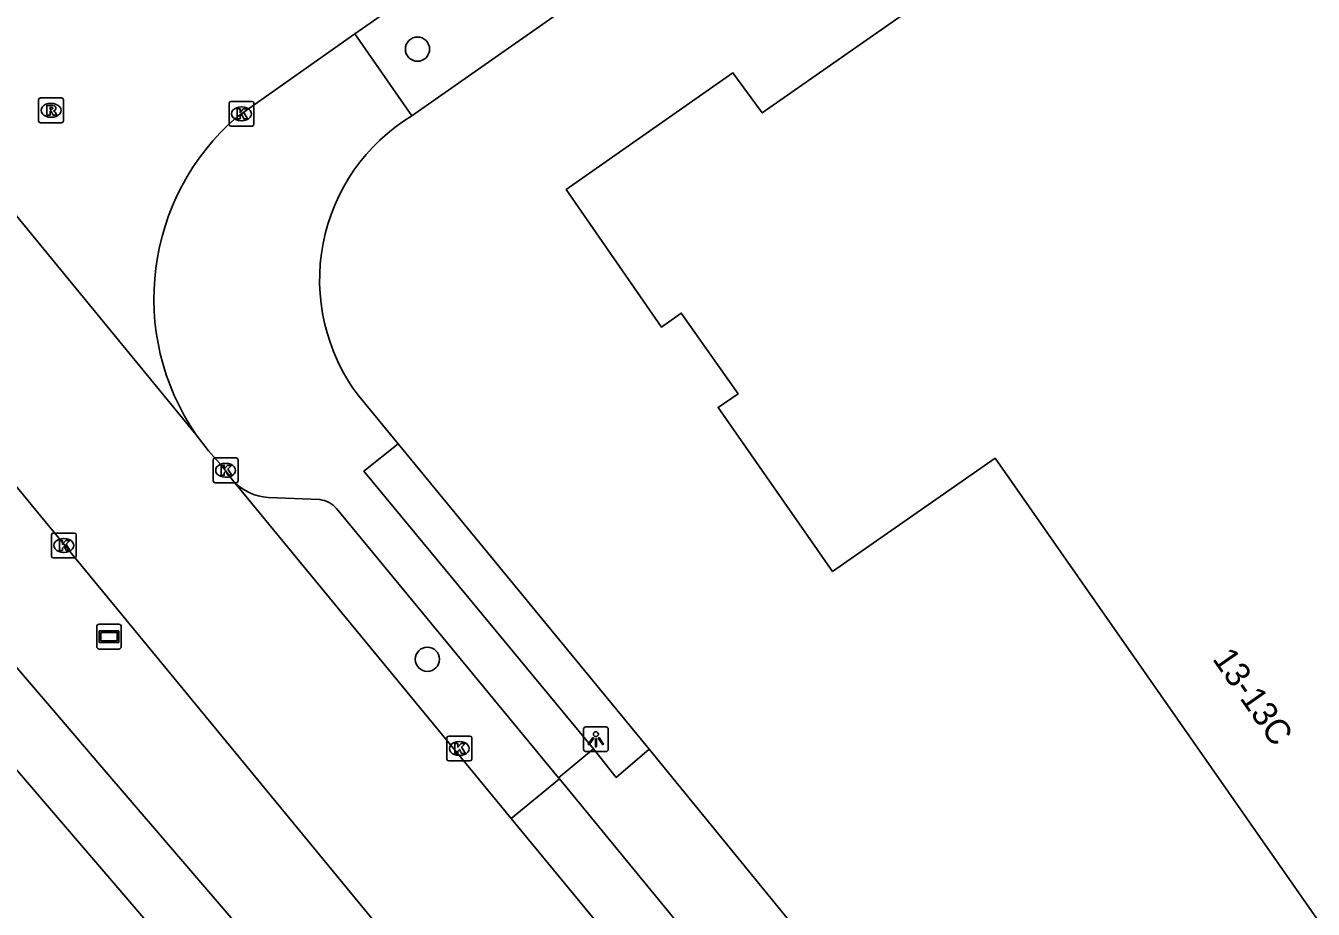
# Model space of a CAD drawing. Extents: x 156651 to 158072, y 387631 to 388990.
# Drawn here: x 157099.8 to 157151.7, y 387934.7 to 387970.3 of the extents above; entities that cross this region are included whole.
import ezdxf

# ---------------------------------------------------------------- set-up
doc = ezdxf.new("R2010")
doc.units = 0
for name, color, linetype in [('IMGEO_Berm_groen', 7, 'Continuous'), ('IMGEO_Boom', 7, 'Continuous'), ('IMGEO_Groenvoorziening', 7, 'Continuous'), ('IMGEO_Kolk', 7, 'Continuous'), ('IMGEO_Lichtpunt', 7, 'Continuous'), ('IMGEO_Pand', 7, 'Continuous'), ('IMGEO_Pand_nummerreeks', 7, 'Continuous'), ('IMGEO_Rijbaan_lokaal_gesloten', 7, 'Continuous'), ('IMGEO_Rioolput', 7, 'Continuous'), ('IMGEO_Spoorbaan_halfverhard', 7, 'Continuous'), ('IMGEO_Verklikker', 7, 'Continuous'), ('IMGEO_Voetpad_open', 7, 'Continuous')]:
    doc.layers.add(name, color=color, linetype=linetype)

msp = doc.modelspace()

# ---------------------------------------------------------------- linework, layer by layer
at = {"layer": 'IMGEO_Berm_groen'}
for points in [[(157115.369, 387966.676), (157132.369, 387978.596)], [(157097.859, 387946.262), (157101.164, 387942.415), (157102.794, 387940.504), (157114.273, 387927.11), (157115.959, 387925.21), (157120.786, 387919.425), (157132.177, 387905.879), (157138.683, 387898.173), (157156.546, 387876.96), (157159.776, 387873.028), (157164.591, 387867.234), (157166.179, 387865.286)]]:
    msp.add_lwpolyline(points, dxfattribs=at)
at = {"layer": 'IMGEO_Boom'}
for centre in [(157115.594, 387969.362), (157115.994, 387944.76)]:
    msp.add_circle(centre, 0.489, dxfattribs=at)
at = {"layer": 'IMGEO_Groenvoorziening'}
msp.add_lwpolyline([(157124.927, 387941.131), (157114.82, 387953.45)], dxfattribs=at)
at = {"layer": 'IMGEO_Kolk'}
for p, q in [((157108.002, 387966.33), (157108.002, 387967.182)), ((157108.077, 387967.256), (157108.929, 387967.256)), ((157108.49, 387967.036), (157108.515, 387967.036)), ((157109.003, 387967.182), (157109.003, 387966.33)), ((157108.513, 387966.476), (157108.488, 387966.476)), ((157108.929, 387966.256), (157108.077, 387966.256)), ((157107.437, 387952.879), (157108.289, 387952.879)), ((157107.362, 387951.953), (157107.362, 387952.805)), ((157107.85, 387952.659), (157107.875, 387952.659)), ((157108.363, 387952.805), (157108.363, 387951.953)), ((157108.289, 387951.879), (157107.437, 387951.879)), ((157107.873, 387952.099), (157107.848, 387952.099)), ((157100.845, 387948.922), (157100.845, 387949.774)), ((157100.92, 387949.848), (157101.772, 387949.848)), ((157101.846, 387949.774), (157101.846, 387948.922)), ((157101.333, 387949.628), (157101.358, 387949.628)), ((157101.772, 387948.848), (157100.92, 387948.848)), ((157101.356, 387949.068), (157101.331, 387949.068)), ((157116.779, 387940.735), (157116.779, 387941.587)), ((157116.854, 387941.661), (157117.706, 387941.661)), ((157117.267, 387941.441), (157117.292, 387941.441)), ((157117.78, 387941.587), (157117.78, 387940.735)), ((157117.29, 387940.881), (157117.265, 387940.881)), ((157117.706, 387940.661), (157116.854, 387940.661))]:
    msp.add_line(p, q, dxfattribs=at)
for points in [[(157108.002, 387966.33), (157108.002, 387967.182)], [(157108.077, 387967.256), (157108.929, 387967.256)], [(157108.323, 387966.956), (157108.446, 387966.956), (157108.446, 387966.805), (157108.576, 387966.956), (157108.74, 387966.956), (157108.594, 387966.805), (157108.747, 387966.556), (157108.595, 387966.556), (157108.51, 387966.72), (157108.446, 387966.653), (157108.446, 387966.556), (157108.323, 387966.556), (157108.323, 387966.956)], [(157109.003, 387967.182), (157109.003, 387966.33)], [(157108.929, 387966.256), (157108.077, 387966.256)], [(157107.437, 387952.879), (157108.289, 387952.879)], [(157107.362, 387951.953), (157107.362, 387952.805)], [(157107.683, 387952.579), (157107.806, 387952.579), (157107.806, 387952.428), (157107.936, 387952.579), (157108.1, 387952.579), (157107.954, 387952.428), (157108.107, 387952.179), (157107.955, 387952.179), (157107.87, 387952.343), (157107.806, 387952.276), (157107.806, 387952.179), (157107.683, 387952.179), (157107.683, 387952.579)], [(157108.363, 387952.805), (157108.363, 387951.953)], [(157108.289, 387951.879), (157107.437, 387951.879)], [(157100.845, 387948.922), (157100.845, 387949.774)], [(157100.92, 387949.848), (157101.772, 387949.848)], [(157101.846, 387949.774), (157101.846, 387948.922)], [(157101.166, 387949.548), (157101.289, 387949.548), (157101.289, 387949.397), (157101.419, 387949.548), (157101.583, 387949.548), (157101.437, 387949.397), (157101.59, 387949.148), (157101.438, 387949.148), (157101.353, 387949.312), (157101.289, 387949.245), (157101.289, 387949.148), (157101.166, 387949.148), (157101.166, 387949.548)], [(157101.772, 387948.848), (157100.92, 387948.848)], [(157116.779, 387940.735), (157116.779, 387941.587)], [(157116.854, 387941.661), (157117.706, 387941.661)], [(157117.78, 387941.587), (157117.78, 387940.735)], [(157117.1, 387941.361), (157117.223, 387941.361), (157117.223, 387941.21), (157117.353, 387941.361), (157117.517, 387941.361), (157117.371, 387941.21), (157117.524, 387940.961), (157117.372, 387940.961), (157117.287, 387941.125), (157117.223, 387941.058), (157117.223, 387940.961), (157117.1, 387940.961), (157117.1, 387941.361)], [(157117.706, 387940.661), (157116.854, 387940.661)]]:
    msp.add_lwpolyline(points, dxfattribs=at)
for centre, start, end in [((157108.079, 387967.18), 91.552, 178.448), ((157108.079, 387967.18), 91.552, 178.448), ((157108.927, 387967.18), 1.552, 88.448), ((157108.927, 387967.18), 1.552, 88.448), ((157108.079, 387966.332), 181.552, 268.448), ((157108.079, 387966.332), 181.552, 268.448), ((157108.927, 387966.332), 271.552, 358.448), ((157108.927, 387966.332), 271.552, 358.448), ((157107.439, 387952.803), 91.552, 178.448), ((157107.439, 387952.803), 91.552, 178.448), ((157108.287, 387952.803), 1.552, 88.448), ((157108.287, 387952.803), 1.552, 88.448), ((157107.439, 387951.955), 181.552, 268.448), ((157107.439, 387951.955), 181.552, 268.448), ((157108.287, 387951.955), 271.552, 358.448), ((157108.287, 387951.955), 271.552, 358.448), ((157100.922, 387949.772), 91.552, 178.448), ((157100.922, 387949.772), 91.552, 178.448), ((157101.77, 387949.772), 1.552, 88.448), ((157101.77, 387949.772), 1.552, 88.448), ((157100.922, 387948.924), 181.552, 268.448), ((157100.922, 387948.924), 181.552, 268.448), ((157101.77, 387948.924), 271.552, 358.448), ((157101.77, 387948.924), 271.552, 358.448), ((157116.856, 387941.585), 91.552, 178.448), ((157116.856, 387941.585), 91.552, 178.448), ((157117.704, 387941.585), 1.552, 88.448), ((157117.704, 387941.585), 1.552, 88.448), ((157116.856, 387940.737), 181.552, 268.448), ((157116.856, 387940.737), 181.552, 268.448), ((157117.704, 387940.737), 271.552, 358.448), ((157117.704, 387940.737), 271.552, 358.448)]:
    msp.add_arc(centre, 0.0765, start, end, dxfattribs=at)
for centre, major_axis, ratio, start_param, end_param in [((157108.489, 387966.756), (-0.387, 0.002), 0.722429, 4.712389, 7.853982), ((157108.514, 387966.756), (-0.39, 0.002), 0.717154, 1.570796, 4.712389), ((157107.849, 387952.379), (-0.387, 0.002), 0.722429, 4.712389, 7.853982), ((157107.874, 387952.379), (-0.39, 0.002), 0.717154, 1.570796, 4.712389), ((157101.332, 387949.348), (-0.387, 0.002), 0.722429, 4.712389, 7.853982), ((157101.357, 387949.348), (-0.39, 0.002), 0.717154, 1.570796, 4.712389), ((157117.266, 387941.161), (-0.387, 0.002), 0.722429, 4.712389, 7.853982), ((157117.291, 387941.161), (-0.39, 0.002), 0.717154, 1.570796, 4.712389)]:
    msp.add_ellipse(centre, major_axis=major_axis, ratio=ratio, start_param=start_param, end_param=end_param, dxfattribs=at)
at = {"layer": 'IMGEO_Lichtpunt'}
for p, q in [((157122.285, 387941.941), (157122.285, 387941.134)), ((157122.285, 387941.941), (157122.285, 387941.134)), ((157123.187, 387942.036), (157122.379, 387942.036)), ((157123.187, 387942.036), (157122.379, 387942.036)), ((157123.281, 387941.134), (157123.281, 387941.941)), ((157123.281, 387941.134), (157123.281, 387941.941)), ((157122.379, 387941.04), (157123.187, 387941.04)), ((157122.379, 387941.04), (157123.187, 387941.04))]:
    msp.add_line(p, q, dxfattribs=at)
for points in [[(157122.659, 387941.605), (157122.698, 387941.577), (157122.51, 387941.315), (157122.472, 387941.342), (157122.659, 387941.605)], [(157122.761, 387941.557), (157122.808, 387941.557), (157122.808, 387941.235), (157122.761, 387941.235), (157122.761, 387941.557)], [(157122.871, 387941.577), (157122.909, 387941.604), (157123.096, 387941.342), (157123.057, 387941.314), (157122.871, 387941.577)]]:
    msp.add_lwpolyline(points, dxfattribs=at)
msp.add_circle((157122.784, 387941.739), 0.0994, dxfattribs=at)
for centre, start, end in [((157122.379, 387941.941), 90, 180), ((157122.379, 387941.941), 90, 180), ((157123.187, 387941.941), 0, 90), ((157123.187, 387941.941), 0, 90), ((157122.379, 387941.134), 180, 270), ((157122.379, 387941.134), 180, 270), ((157123.187, 387941.134), 270, 0), ((157123.187, 387941.134), 270, 360)]:
    msp.add_arc(centre, 0.0946, start, end, dxfattribs=at)
at = {"layer": 'IMGEO_Pand'}
msp.add_lwpolyline([(157176.445, 387993.484), (157173.582, 387997.583), (157129.48, 387966.798), (157128.305, 387968.4), (157121.58, 387963.701), (157125.426, 387958.155), (157126.221, 387958.716), (157128.512, 387955.46), (157127.71, 387954.912), (157132.324, 387948.299), (157138.872, 387952.869), (157155.624, 387928.882), (157160.137, 387932.027), (157175.566, 387942.779), (157162.397, 387961.636), (157186.784, 387978.673), (157176.445, 387993.484)], dxfattribs=at)
at = {"layer": 'IMGEO_Rijbaan_lokaal_gesloten'}
for points in [[(157113.073, 387969.976), (157129.211, 387981.246)], [(157090.708, 387973.286), (157106.681, 387953.807)], [(157108.323, 387966.633), (157113.073, 387969.976)], [(157168.303, 387867.992), (157086.65, 387967.254)], [(157108.17, 387951.954), (157107.707, 387952.557), (157107.168, 387953.161), (157106.681, 387953.807)], [(157119.374, 387938.343), (157108.17, 387951.954)], [(157127.008, 387929.069), (157119.374, 387938.343)]]:
    msp.add_lwpolyline(points, dxfattribs=at)
msp.add_arc((157114.662, 387959.303), 9.691, 130.8559, 214.5533, dxfattribs=at)
at = {"layer": 'IMGEO_Rioolput'}
for p, q in [((157100.403, 387967.394), (157101.255, 387967.394)), ((157100.328, 387966.468), (157100.328, 387967.32)), ((157100.816, 387967.174), (157100.841, 387967.174)), ((157101.329, 387967.32), (157101.329, 387966.468)), ((157101.255, 387966.394), (157100.403, 387966.394)), ((157100.839, 387966.614), (157100.814, 387966.614))]:
    msp.add_line(p, q, dxfattribs=at)
for points in [[(157100.403, 387967.394), (157101.255, 387967.394)], [(157100.328, 387966.468), (157100.328, 387967.32)], [(157100.917, 387967.092), (157100.665, 387967.094), (157100.665, 387966.694)], [(157100.665, 387966.694), (157100.789, 387966.694), (157100.789, 387966.856), (157100.8, 387966.856)], [(157100.843, 387967.013), (157100.789, 387967.013), (157100.789, 387966.932)], [(157100.789, 387966.932), (157100.841, 387966.932)], [(157100.847, 387966.827), (157100.918, 387966.694), (157101.058, 387966.694), (157100.993, 387966.82)], [(157101.329, 387967.32), (157101.329, 387966.468)], [(157101.255, 387966.394), (157100.403, 387966.394)]]:
    msp.add_lwpolyline(points, dxfattribs=at)
for centre, radius, start, end in [((157100.405, 387967.318), 0.0765, 91.552, 178.448), ((157100.405, 387967.318), 0.0765, 91.552, 178.448), ((157101.253, 387967.318), 0.0765, 1.552, 88.448), ((157101.253, 387967.318), 0.0765, 1.552, 88.448), ((157100.799, 387966.803), 0.0533, 26.0293, 88.6989), ((157100.825, 387967.121), 0.19, 274.7715, 282.9687), ((157100.849, 387966.917), 0.0964, 77.0061, 93.1865), ((157100.863, 387966.974), 0.0378, 276.6634, 79.6772), ((157100.916, 387966.982), 0.109, 350.3612, 89.416), ((157100.914, 387966.982), 0.112, 277.5842, 350.9817), ((157100.898, 387966.767), 0.108, 29.5134, 73.7905), ((157100.405, 387966.47), 0.0765, 181.552, 268.448), ((157100.405, 387966.47), 0.0765, 181.552, 268.448), ((157101.253, 387966.47), 0.0765, 271.552, 358.448), ((157101.253, 387966.47), 0.0765, 271.552, 358.448)]:
    msp.add_arc(centre, radius, start, end, dxfattribs=at)
for centre, major_axis, ratio, start_param, end_param in [((157100.815, 387966.894), (-0.387, 0.002), 0.722429, 4.712389, 7.853982), ((157100.84, 387966.894), (-0.39, 0.002), 0.717154, 1.570796, 4.712389)]:
    msp.add_ellipse(centre, major_axis=major_axis, ratio=ratio, start_param=start_param, end_param=end_param, dxfattribs=at)
at = {"layer": 'IMGEO_Spoorbaan_halfverhard'}
msp.add_lwpolyline([(157157.305, 387872.588), (157123.947, 387911.695), (157068.122, 387976.848), (157042.808, 388006.065), (156962.414, 388099.504), (156929.103, 388138.77), (156911.81, 388159.683), (156885.921, 388191.403), (156881.34, 388197.231)], dxfattribs=at)
at = {"layer": 'IMGEO_Verklikker'}
for p, q in [((157102.669, 387945.273), (157102.669, 387946.073)), ((157102.669, 387946.073), (157102.669, 387945.273)), ((157102.769, 387946.173), (157103.559, 387946.173)), ((157103.559, 387946.173), (157102.769, 387946.173)), ((157103.659, 387946.073), (157103.659, 387945.273)), ((157103.659, 387945.273), (157103.659, 387946.073)), ((157103.559, 387945.173), (157102.769, 387945.173)), ((157102.769, 387945.173), (157103.559, 387945.173))]:
    msp.add_line(p, q, dxfattribs=at)
for points in [[(157102.77, 387945.905), (157103.558, 387945.905), (157103.558, 387945.441), (157102.77, 387945.441), (157102.77, 387945.905)], [(157102.835, 387945.84), (157102.835, 387945.506), (157103.493, 387945.506), (157103.493, 387945.84), (157102.835, 387945.84)]]:
    msp.add_lwpolyline(points, dxfattribs=at)
for centre, start, end in [((157102.769, 387946.073), 90, 180), ((157102.769, 387946.073), 90, 180), ((157103.559, 387946.073), 0, 90), ((157103.559, 387946.073), 360, 90), ((157102.769, 387945.273), 180, 270), ((157102.769, 387945.273), 180, 270), ((157103.559, 387945.273), 270, 0), ((157103.559, 387945.273), 270, 0)]:
    msp.add_arc(centre, 0.1, start, end, dxfattribs=at)
at = {"layer": 'IMGEO_Voetpad_open'}
for points in [[(157115.369, 387966.676), (157113.073, 387969.976)], [(157114.82, 387953.45), (157113.203, 387955.403)], [(157122.692, 387941.15), (157113.438, 387952.35), (157114.82, 387953.45)], [(157109.578, 387951.283), (157111.656, 387951.196)], [(157112.333, 387950.836), (157121.281, 387939.976)], [(157121.281, 387939.976), (157122.692, 387941.15)], [(157122.692, 387941.15), (157123.602, 387939.994), (157124.927, 387941.131)], [(157130.787, 387933.959), (157124.927, 387941.131)], [(157121.312, 387939.938), (157119.374, 387938.343)], [(157121.281, 387939.976), (157121.312, 387939.938)], [(157121.312, 387939.938), (157128.869, 387930.731)]]:
    msp.add_lwpolyline(points, dxfattribs=at)
for centre, radius, start, end in [((157119.399, 387960.057), 7.749, 121.3342, 216.9132), ((157109.681, 387953.312), 2.031, 221.9438, 267.0948), ((157111.543, 387950.167), 1.035, 40.2669, 83.7288)]:
    msp.add_arc(centre, radius, start, end, dxfattribs=at)

# ---------------------------------------------------------------- texts
at = {"layer": 'IMGEO_Pand_nummerreeks'}
msp.add_text('13-13C', height=1, rotation=304.9273, dxfattribs=at).set_placement((157147.598, 387944.777))

doc.saveas('drawing.dxf')
